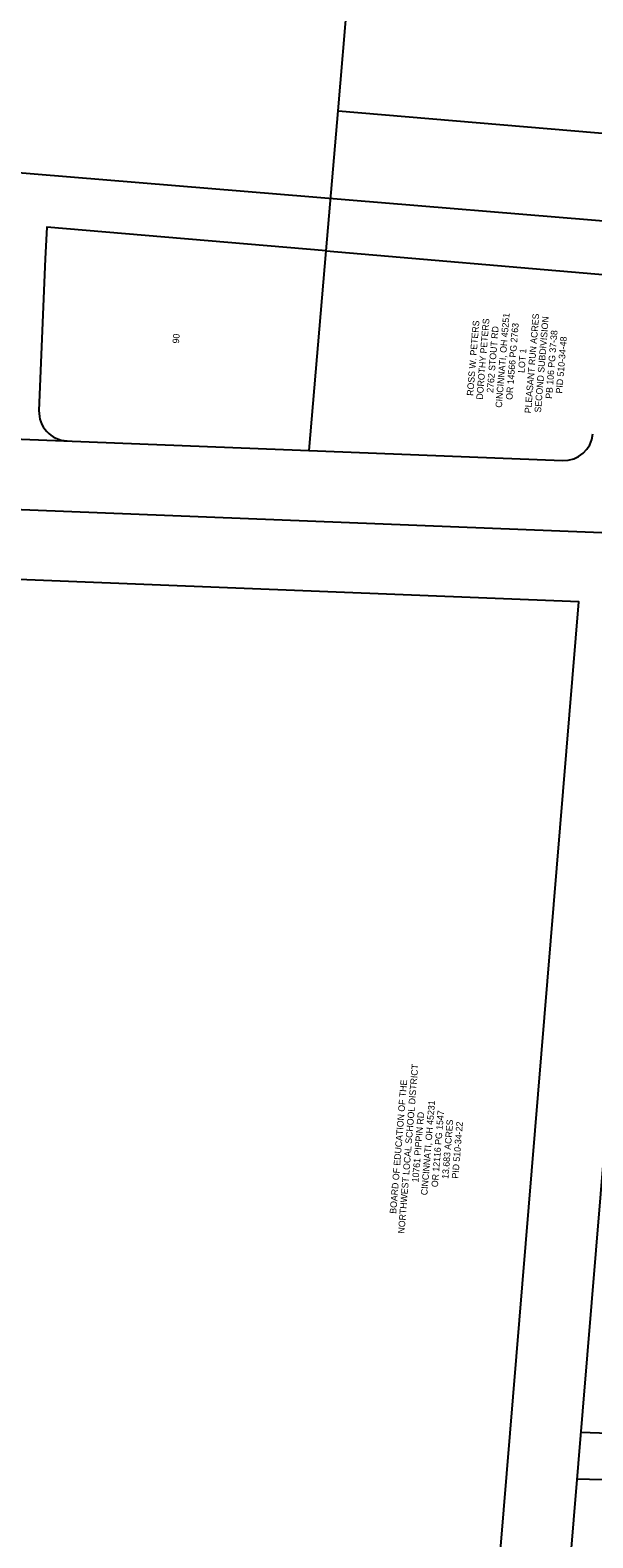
# Model space of a CAD drawing. Extents: x 1379776 to 1382941, y 467490 to 471592.
# Drawn here: x 1381356 to 1381596, y 469835 to 470478 of the extents above; entities that cross this region are included whole.
import ezdxf

# ---------------------------------------------------------------- set-up
doc = ezdxf.new("R2010")
doc.units = 0
for name, color, linetype in [('PV_P_Drive', 7, 'Continuous'), ('PV_X_Driveway', 7, 'Continuous'), ('RC_X_Text', 7, 'Continuous'), ('RD_X_Wall', 7, 'Continuous'), ('SH_Named_Boundary', 7, 'Continuous')]:
    doc.layers.add(name, color=color, linetype=linetype)

msp = doc.modelspace()

# ---------------------------------------------------------------- linework, layer by layer
at = {"layer": 'PV_P_Drive'}
for p, q in [((1381487.23, 470443.68), (1381492.3, 470503.46)), ((1381482.15, 470383.89), (1381487.23, 470443.68)), ((1381487.22, 470443.68), (1381606.79, 470433.53)), ((1381474.92, 470298.7), (1381482.15, 470383.89)), ((1381482.15, 470383.89), (1381601.72, 470373.74)), ((1380559.29, 470305.26), (1381622.42, 470262.79)), ((1381622.42, 470262.79), (1381580.75, 469758.51)), ((1381590.76, 469879.68), (1381771.53, 469873.97)), ((1381889.85, 469850.22), (1381589.11, 469859.72))]:
    msp.add_line(p, q, dxfattribs=at)
msp.add_lwpolyline([(1381482.15, 470383.89), (1381362.84, 470394.02), (1381362.13, 470380.46), (1381359.54, 470315.82)], dxfattribs=at)
msp.add_arc((1381372.03, 470315.32), 12.5, 177.71231, 267.71231, dxfattribs=at)
at = {"layer": 'PV_X_Driveway'}
msp.add_lwpolyline([(1381481.91, 468926.74), (1381589.94, 470234.06), (1380557.84, 470275.29)], dxfattribs=at)
at = {"layer": 'RD_X_Wall'}
msp.add_line((1380560.49, 470335.24), (1381583.03, 470294.39), dxfattribs=at)
msp.add_arc((1381583.49, 470306.88), 12.5, 267.78762, 355.22531, dxfattribs=at)
at = {"layer": 'SH_Named_Boundary'}
msp.add_lwpolyline([(1381019.66, 469039.84), (1381836.87, 468972.31), (1381848.4, 469111.83), (1381859.93, 469251.36), (1381871.46, 469390.88), (1381882.99, 469530.4), (1381894.52, 469669.93), (1381906.05, 469809.45), (1381917.58, 469948.98), (1381929.11, 470088.5), (1381940.64, 470228.03), (1381952.16, 470367.55), (1381134.95, 470435.08), (1381123.42, 470295.56), (1381111.89, 470156.03), (1381100.36, 470016.51), (1381088.83, 469876.98), (1381077.3, 469737.46), (1381065.77, 469597.93), (1381054.24, 469458.41), (1381042.71, 469318.88), (1381031.19, 469179.36)], close=True, dxfattribs=at)

# ---------------------------------------------------------------- texts
at = {"layer": 'RC_X_Text'}
for s, p in [('ROSS W. PETERS', (1381544.88, 470321.95)), ('DOROTHY PETERS', (1381548.96, 470320.34)), ('2762 STOUT RD', (1381553.42, 470323.27)), ('CINCINNATI, OH 45251', (1381557.11, 470316.88)), ('OR 14566 PG 2763', (1381561.6, 470320.25)), ('PLEASANT RUN ACRES', (1381569.56, 470314.53)), ('SECOND SUBDIVISION', (1381573.79, 470314.82)), ('90', (1381419.28, 470344.3)), ('PB 106 PG 37-38', (1381578.49, 470320.69)), ('PID 510-34-48', (1381582.89, 470322.95)), ('LOT 1', (1381566.76, 470331.75)), ('NORTHWEST LOCAL SCHOOL DISTRICT', (1381515.5, 469964.38)), ('BOARD OF EDUCATION OF THE', (1381511.99, 469972.85)), ('CINCINNATI, OH 45231', (1381525.29, 469980.75)), ('OR 12116 PG 1547', (1381529.78, 469984.18)), ('10761 PIPPIN RD', (1381521.52, 469986.23)), ('13.683 ACRES', (1381534.29, 469987.73)), ('PID 510-34-22', (1381538.52, 469987.85))]:
    msp.add_text(s, height=2.8, rotation=85.27618, dxfattribs=at).set_placement(p)

doc.saveas('drawing.dxf')
